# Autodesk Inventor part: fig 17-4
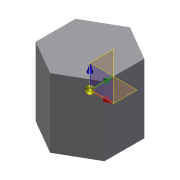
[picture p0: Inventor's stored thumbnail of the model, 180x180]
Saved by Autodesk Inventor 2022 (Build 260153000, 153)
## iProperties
Created: 2008-06
Part Number: fig 17-4
Document SubType Name: Modeling
Designer: CADCIM
Mass: 866.025 g
Surface Area: 519.615 cm^2
Volume: 866.025 cm^3
Density: 1 g/cm^3
Material: Generic
Appearance: Default
Author: CADCIM
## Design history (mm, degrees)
sketch "Sketch1"
  geometry: L1 (0.184, 57.735)-(50.092, 28.708); L2 (50.092, 28.708)-(49.908, -29.027); L3 (49.908, -29.027)-(-0.184, -57.735); L4 (-0.184, -57.735)-(-50.092, -28.708); L5 (-50.092, -28.708)-(-49.908, 29.027); L6 (-49.908, 29.027)-(0.184, 57.735); 1 further point
  constraints: 12 end point, 13 other
  dimensions: "d0" = 100 distance between parallel lines of L2 L5
extrude "Extrusion1" new body sketch "Sketch1" distance "d1" = 100; taper "d2" = 0 deg
body "Solid1"
